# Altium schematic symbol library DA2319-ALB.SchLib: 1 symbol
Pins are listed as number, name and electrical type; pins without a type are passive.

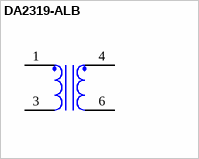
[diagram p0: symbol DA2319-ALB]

## DA2319-ALB
designator X?
Manufacturer: Coilcraft; SymbolVersion: use current date i.e. 2008-05-20; SymbolCreator: Use a-id; CompType: Transformer; U/M: EA; Description: Transformer, 296 uH, SMT; Value: 296 uH
pins: 1, 3, 4, 6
